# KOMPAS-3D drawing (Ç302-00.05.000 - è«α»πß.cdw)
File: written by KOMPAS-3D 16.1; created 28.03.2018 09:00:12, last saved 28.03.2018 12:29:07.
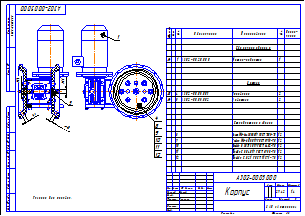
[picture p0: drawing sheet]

Sheet 1: A3, landscape

Title block, sheet 1: name: Корпус; designation: А302-00.05.000; mass: 29,42; scale: 1:4; sheets: 1; organisation: ЗАО «Астерион»; sheet format: A3; stored path: Z:\Мембранные насосы\Мембранный электропривод\А302-00.00.000 - ASTRA-302 (МЭ200)\Чертежи\А302-00.05.000 - Корпус.cdw; drawn by: Милов; technical control: Лучихин

Referenced files in Z:\Мембранные насосы\Мембранный электропривод\А302-00.00.000 - ASTRA-302 (МЭ200)\Чертежи\: А302-00.20.000  - Мотор-редуктор.spw
Referenced files in \\192.168.87.28\Konstructor_doc\Мембранные насосы\Мембранный электропривод\А302-00.00.000 - ASTRA-302 (МЭ200)\Чертежи\: А302-00.05.002 - Ловитель.cdw, А302-00.05.001 - Основание.cdw
Referenced files: GRAPHIC.TDP
Referenced files in Z:\Мембранные насосы\Мембранный электропривод\А302-00.00.000 - ASTRA-302 (МЭ200)\3Д\: А302-00.05.000 - Корпус.a3d, А302-00.20.001 - Основание.m3d, А302-00.35.002 - Пластина.m3d, А302-00.35.001 - Труба 140х140х4.m3d, А302-00.35.000 - Фланец.a3d, А302-00.20.002 - Эксцентрик.m3d, А302-00.20.004 - Вал.m3d, А302-00.20.003 - Ползун.m3d, А302-00.20.000 - Мотор-редуктор.a3d, А302-00.05.002 - Ловитель.m3d, А302-00.05.001 - Основание.m3d
Referenced files in Z:\1 ПКИ 3D\Двигатели\АИР\: Электродвигатель АИР 80А4 IM 3081 1,1кВт 1400 об..m3d
Referenced files in Z:\1 ПКИ 3D\Редуктора NMRW\Редукторы\: Редуктор NMRW 063.m3d, Червячный мотор-редуктор NMRV063 АИР80.a3d
Referenced files in C:\Program Files\ASCON\KOMPAS-3D V16\Libs\PartLib\DATA\vault\Methods\Kompas\3D\: PLib_Check_spring_rings_GOST_13942_911.m3d, PLib_Nut_OST92_900.m3d, PLib_Screw_DIN_7984_1500.m3d, PLib_Key_prismatic_712.m3d
Referenced files in Z:\1 ПКИ 3D\1 Крепеж стандартный\Подшипник\: Подшипник 52х25х15 62052RSH SKF.m3d
Referenced files in C:\Program Files\ASCON\KOMPAS-3D V16\Libs\PartLib\DATA\VAULT\Methods\kompas\3d\: PLib_Washer_1_712.m3d, PLib_Bolt_1_900.m3d, PLib_Washer_2_712.m3d
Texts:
  Размеры для справок.
  Мотор-редуктор
  Ловитель
  Основание
  Шайба C.8.21 ГОСТ 11371-78
  Крепежное изделие ГОСТ
  Шайба
  ГОСТ
  Сталь 12Х18Н10Т ГОСТ 5632-72
  Шайба C 8.04.019 ГОСТ 6958-78
  Сталь 20 ГОСТ 1050-2013
  Шайба 8 30Х13 019 ГОСТ 6402-70
  Сталь 30Х13 ГОСТ 5632-72
  Болт М8-6gx30.58.019 ГОСТ 7805-70
  Болт
  Гайка М8-6H.5.019 ГОСТ 5915-70
  Гайка
  Лит-Масса-Масштаб
  Материал-Предприятие
  Title Specification
  Body Specification ( left align )
  Body Specificaton ( centered )
  Поз.
  Кол.
  Приме-
  чание
  Таблица спецификации
  Электродвигатель АИР 80А4 IM 3081 1,1кВт 1400 об.
  Редуктор NMRW 063
  Червячный мотор-редуктор NMRV063 АИР80
  Пластина
  Труба 140х140х4
  Фланец
  Эксцентрик
  Кольцо A25.65Г ГОСТ 13942-86
  Подшипник 52х25х15 62052RSH SKF
  Вал
  Ползун
  Шайба C.5.04.019 ГОСТ 11371-78
  Болт М5-6gx35.58.019 ГОСТ 7805-70
  Шайба 5 30Х13 019 ГОСТ 6402-70
  Гайка М5-6H.5.019 ГОСТ 5915-70
  Шайба C.8.04.019 ГОСТ 11371-78
  Винт с цилиндрической головкой и шестигранным углублением под ключ ГОСТ Р ИСО 4762 - М8 x 20 - 6.8 - A9J
  Винт с цилиндрической головкой и шестигранным углублением под ключ ГОСТ Р ИСО 4762 - М8 x 35 - 6.8 - A9J
  Шпонка 8x7x90 ГОСТ 23360-78
Dimensions and other numbers on the sheet: 4; 1; 5; 12; 21; 40Х; 019; 11; 8; 04; 10; 58; 30Х13; 9; 1:4; 29,42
